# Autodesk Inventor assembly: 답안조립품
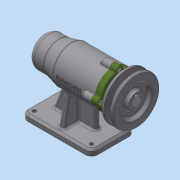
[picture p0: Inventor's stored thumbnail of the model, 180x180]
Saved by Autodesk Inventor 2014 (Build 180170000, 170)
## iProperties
Created: 2019-07
Part Number: 답안조립품
Document SubType Name: Assembly
Designer: mm
Author: mm
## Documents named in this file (12)
- C:\Users\mm\Desktop\490704V1082\답안조립품.iam
- C:\Users\mm\Desktop\490704V1082\본체.ipt
- C:\Users\mm\Desktop\490704V1082\베어링 6004.ipt
- C:\Users\mm\Desktop\490704V1082\커버.ipt
- C:\Users\mm\Desktop\490704V1082\어댑터슬리브.ipt
- C:\Users\mm\Desktop\490704V1082\축.ipt
- C:\Users\mm\Desktop\490704V1082\베어링 51202.ipt
- C:\Users\mm\Desktop\490704V1082\볼트 M4.ipt
- C:\Users\mm\Desktop\490704V1082\오일 실.ipt
- C:\Users\mm\Desktop\490704V1082\키 5 x 5 x 16.ipt
- C:\Users\mm\Desktop\490704V1082\V벨트풀리.ipt
- C:\Users\mm\Desktop\490704V1082\멈춤나사 M3.ipt
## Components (1 placed, 1 different names)
1. V벨트풀리:1 — 플러쉬:2, 각도:1
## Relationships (2: Flush 1, Angle 1)
- 플러쉬:2 [Flush]: V벨트풀리:1
- 각도:1 [Angle]: V벨트풀리:1
